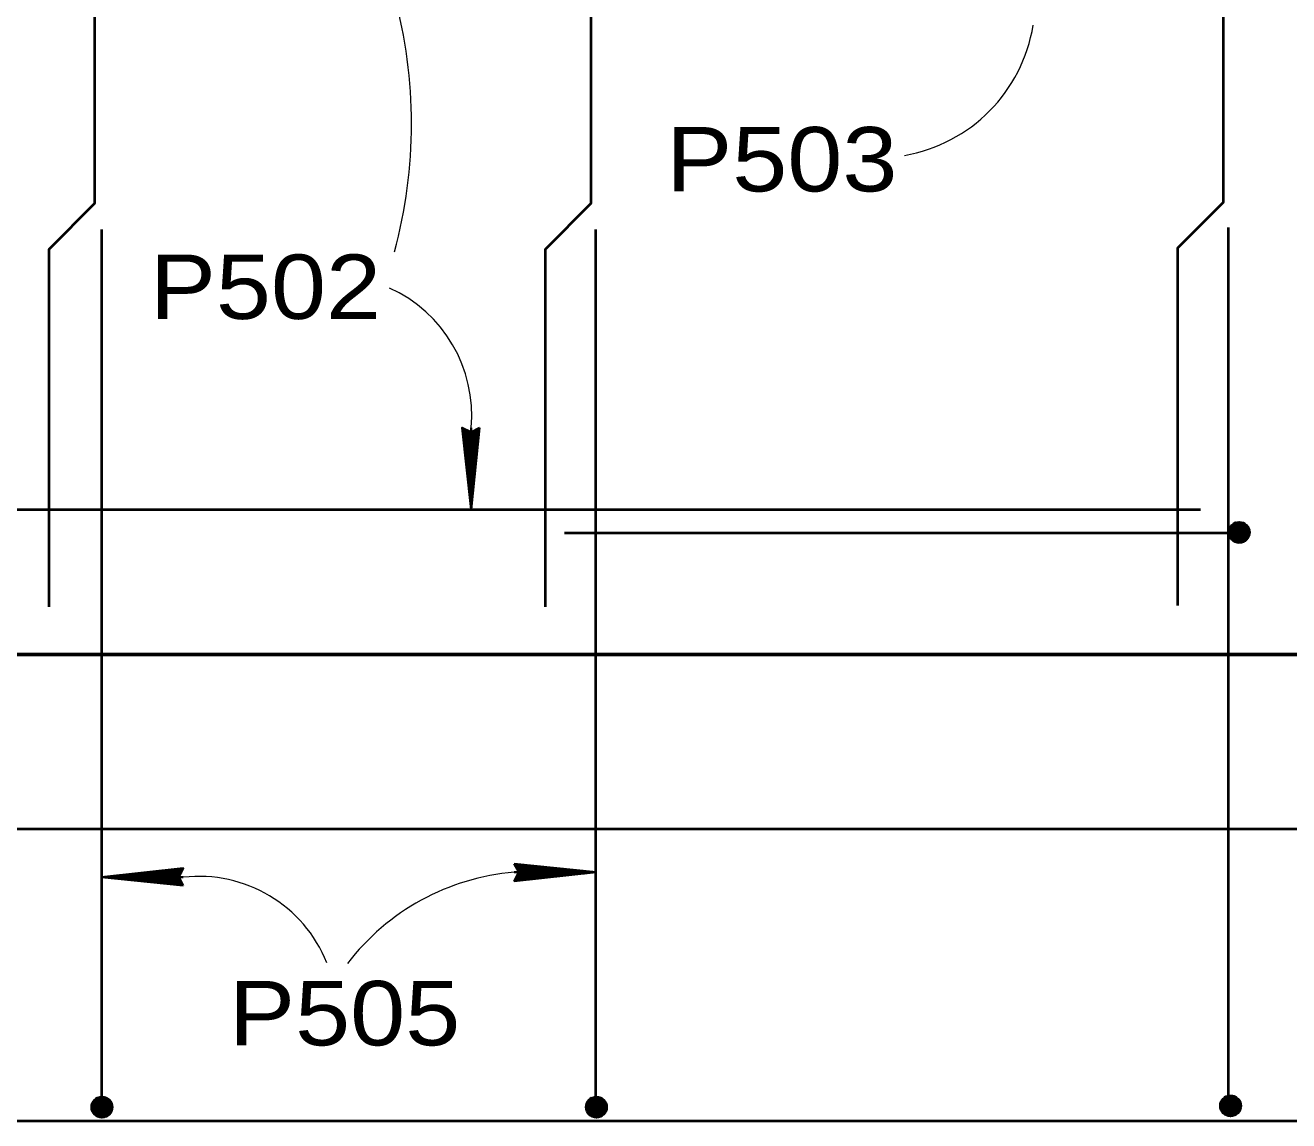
# Model space of a CAD drawing. Extents: x 4.49 to 7.69, y 0.28 to 2.27.
# Drawn here: x 5.2955 to 5.4591, y 0.6221 to 0.7638 of the extents above; entities that cross this region are included whole.
import ezdxf

# ---------------------------------------------------------------- set-up
doc = ezdxf.new("R2010")
doc.units = 0
doc.header["$LTSCALE"] = 0.0033
doc.layers.add('1', color=7, linetype='Continuous', lineweight=35)

msp = doc.modelspace()

# ---------------------------------------------------------------- linework, layer by layer
at = {"layer": '1', "lineweight": 40}
for p, q in [((5.45125, 0.737667), (5.45125, 0.625333)), ((5.305417, 0.737417), (5.305417, 0.624917)), ((5.369333, 0.737417), (5.369333, 0.625)), ((5.45175, 0.699), (5.451667, 0.6975)), ((5.451667, 0.6985), (5.453667, 0.698167)), ((5.451667, 0.698417), (5.453667, 0.698)), ((5.451667, 0.698333), (5.453583, 0.697917)), ((5.451833, 0.699), (5.45175, 0.6975)), ((5.45175, 0.699), (5.45375, 0.698667)), ((5.45175, 0.698917), (5.45375, 0.698583)), ((5.45175, 0.698833), (5.45375, 0.698417)), ((5.45175, 0.69875), (5.45375, 0.698333)), ((5.45175, 0.698583), (5.453667, 0.69825)), ((5.451833, 0.699167), (5.45375, 0.698833)), ((5.451917, 0.699), (5.451833, 0.6975)), ((5.452, 0.699), (5.451917, 0.6975)), ((5.452083, 0.699), (5.452, 0.6975)), ((5.45225, 0.699), (5.452167, 0.6975)), ((5.452333, 0.699), (5.45225, 0.6975)), ((5.452417, 0.699), (5.452333, 0.6975)), ((5.4525, 0.699), (5.452417, 0.6975)), ((5.452583, 0.699), (5.4525, 0.6975)), ((5.452667, 0.699), (5.452583, 0.6975)), ((5.45275, 0.699), (5.452667, 0.6975)), ((5.452917, 0.698917), (5.45275, 0.697417)), ((5.453083, 0.698917), (5.452917, 0.697417)), ((5.453167, 0.698917), (5.453083, 0.697417)), ((5.453167, 0.698917), (5.453083, 0.697417)), ((5.45325, 0.698917), (5.453167, 0.697417)), ((5.453333, 0.698917), (5.45325, 0.697417)), ((5.453417, 0.698917), (5.453333, 0.697417)), ((5.4535, 0.698917), (5.453417, 0.697417)), ((5.453583, 0.698917), (5.4535, 0.697417)), ((5.453667, 0.698917), (5.453583, 0.697417)), ((5.453833, 0.698917), (5.45375, 0.697417)), ((5.365333, 0.698167), (5.45125, 0.698167)), ((5.4515, 0.697583), (5.4535, 0.69725)), ((5.451583, 0.698083), (5.453583, 0.697667)), ((5.451583, 0.697833), (5.453583, 0.6975)), ((5.451583, 0.69775), (5.4535, 0.697417)), ((5.451583, 0.697667), (5.4535, 0.697333)), ((5.451667, 0.69825), (5.453583, 0.697833)), ((5.304833, 0.625), (5.3045, 0.623)), ((5.304917, 0.624917), (5.304583, 0.623)), ((5.305, 0.624917), (5.304667, 0.623)), ((5.305083, 0.624917), (5.30475, 0.622917)), ((5.30625, 0.62475), (5.30475, 0.624833)), ((5.30625, 0.624667), (5.30475, 0.62475)), ((5.305333, 0.624917), (5.304917, 0.622917)), ((5.3055, 0.624833), (5.305083, 0.622917)), ((5.305583, 0.624833), (5.305167, 0.622917)), ((5.305667, 0.624833), (5.30525, 0.622833)), ((5.30575, 0.624833), (5.305417, 0.622833)), ((5.305833, 0.62475), (5.3055, 0.622833)), ((5.306, 0.62475), (5.305583, 0.62275)), ((5.306083, 0.62475), (5.305667, 0.62275)), ((5.306167, 0.62475), (5.305833, 0.62275)), ((5.30625, 0.62475), (5.305917, 0.62275)), ((5.368833, 0.625), (5.3685, 0.623)), ((5.368917, 0.624917), (5.368583, 0.623)), ((5.369, 0.624917), (5.368667, 0.623)), ((5.369083, 0.624917), (5.36875, 0.622917)), ((5.37025, 0.62475), (5.36875, 0.624833)), ((5.37025, 0.624667), (5.36875, 0.62475)), ((5.369333, 0.624917), (5.368917, 0.622917)), ((5.3695, 0.624833), (5.369083, 0.622917)), ((5.369583, 0.624833), (5.369167, 0.622917)), ((5.369667, 0.624833), (5.36925, 0.622833)), ((5.36975, 0.624833), (5.369417, 0.622833)), ((5.369833, 0.62475), (5.3695, 0.622833)), ((5.37, 0.62475), (5.369583, 0.62275)), ((5.370083, 0.62475), (5.369667, 0.62275)), ((5.370167, 0.62475), (5.369833, 0.62275)), ((5.37025, 0.62475), (5.369917, 0.62275)), ((5.450917, 0.625167), (5.450583, 0.623167)), ((5.451, 0.625083), (5.450667, 0.623167)), ((5.451083, 0.625083), (5.45075, 0.623167)), ((5.451167, 0.625083), (5.450833, 0.623083)), ((5.452333, 0.624917), (5.450833, 0.625)), ((5.452333, 0.624833), (5.450833, 0.624917)), ((5.452333, 0.62475), (5.450833, 0.624833)), ((5.452333, 0.624667), (5.450833, 0.62475)), ((5.451417, 0.625083), (5.451, 0.623083)), ((5.451583, 0.625), (5.451167, 0.623083)), ((5.451667, 0.625), (5.45125, 0.623083)), ((5.45175, 0.625), (5.451333, 0.623)), ((5.451833, 0.625), (5.4515, 0.623)), ((5.451917, 0.624917), (5.451583, 0.623)), ((5.452083, 0.624917), (5.451667, 0.622917)), ((5.452167, 0.624917), (5.45175, 0.622917)), ((5.45225, 0.624917), (5.451917, 0.622917)), ((5.452333, 0.624917), (5.452, 0.622917)), ((5.4525, 0.624833), (5.452167, 0.622917)), ((5.306167, 0.623583), (5.304667, 0.62375)), ((5.306167, 0.623417), (5.304667, 0.623583)), ((5.306167, 0.623333), (5.304667, 0.623417)), ((5.306167, 0.623333), (5.304667, 0.623417)), ((5.306167, 0.62325), (5.304667, 0.623333)), ((5.306167, 0.623167), (5.304667, 0.62325)), ((5.306167, 0.623083), (5.304667, 0.623167)), ((5.30625, 0.624583), (5.30475, 0.624667)), ((5.30625, 0.6245), (5.30475, 0.624583)), ((5.30625, 0.624417), (5.30475, 0.6245)), ((5.30625, 0.62425), (5.30475, 0.624333)), ((5.30625, 0.624167), (5.30475, 0.62425)), ((5.30625, 0.624083), (5.30475, 0.624167)), ((5.30625, 0.624), (5.30475, 0.624083)), ((5.30625, 0.623917), (5.30475, 0.624)), ((5.30625, 0.623833), (5.30475, 0.623917)), ((5.30625, 0.62375), (5.30475, 0.623833)), ((5.306417, 0.624667), (5.306083, 0.62275)), ((5.370167, 0.623583), (5.368667, 0.62375)), ((5.370167, 0.623417), (5.368667, 0.623583)), ((5.370167, 0.623333), (5.368667, 0.623417)), ((5.370167, 0.623333), (5.368667, 0.623417)), ((5.370167, 0.62325), (5.368667, 0.623333)), ((5.370167, 0.623167), (5.368667, 0.62325)), ((5.370167, 0.623083), (5.368667, 0.623167)), ((5.37025, 0.624583), (5.36875, 0.624667)), ((5.37025, 0.6245), (5.36875, 0.624583)), ((5.37025, 0.624417), (5.36875, 0.6245)), ((5.37025, 0.62425), (5.36875, 0.624333)), ((5.37025, 0.624167), (5.36875, 0.62425)), ((5.37025, 0.624083), (5.36875, 0.624167)), ((5.37025, 0.624), (5.36875, 0.624083)), ((5.37025, 0.623917), (5.36875, 0.624)), ((5.37025, 0.623833), (5.36875, 0.623917)), ((5.37025, 0.62375), (5.36875, 0.623833)), ((5.370417, 0.624667), (5.370083, 0.62275)), ((5.45225, 0.62375), (5.45075, 0.623917)), ((5.45225, 0.623583), (5.45075, 0.62375)), ((5.45225, 0.6235), (5.45075, 0.623583)), ((5.45225, 0.6235), (5.45075, 0.623583)), ((5.45225, 0.623417), (5.45075, 0.6235)), ((5.45225, 0.623333), (5.45075, 0.623417)), ((5.45225, 0.62325), (5.45075, 0.623333)), ((5.45225, 0.623167), (5.45075, 0.62325)), ((5.45225, 0.623083), (5.45075, 0.623167)), ((5.452333, 0.624583), (5.450833, 0.624667)), ((5.452333, 0.624417), (5.450833, 0.6245)), ((5.452333, 0.624333), (5.450833, 0.624417)), ((5.452333, 0.62425), (5.450833, 0.624333)), ((5.452333, 0.624167), (5.450833, 0.62425)), ((5.452333, 0.624083), (5.450833, 0.624167)), ((5.452333, 0.624), (5.450833, 0.624083)), ((5.452333, 0.623917), (5.450833, 0.624)), ((5.306167, 0.623), (5.304667, 0.623083)), ((5.306167, 0.622917), (5.304667, 0.623)), ((5.306167, 0.622833), (5.304667, 0.622917)), ((5.306167, 0.622667), (5.304667, 0.62275)), ((5.370167, 0.623), (5.368667, 0.623083)), ((5.370167, 0.622917), (5.368667, 0.623)), ((5.370167, 0.622833), (5.368667, 0.622917)), ((5.370167, 0.622667), (5.368667, 0.62275)), ((5.45225, 0.623), (5.45075, 0.623083)), ((5.45225, 0.622833), (5.45075, 0.622917))]:
    msp.add_line(p, q, dxfattribs=at)
at = {"layer": '1'}
for p, q in [((5.352167, 0.7115), (5.353, 0.704167)), ((5.352333, 0.7115), (5.353083, 0.704167)), ((5.352417, 0.7115), (5.35325, 0.704167)), ((5.352583, 0.711583), (5.353333, 0.70425)), ((5.354083, 0.7115), (5.353083, 0.703667)), ((5.35325, 0.71175), (5.35325, 0.701167)), ((5.354083, 0.7115), (5.35325, 0.703667)), ((5.35425, 0.7115), (5.353333, 0.703667)), ((5.35425, 0.7115), (5.353333, 0.703667)), ((5.354167, 0.7115), (5.353333, 0.703667)), ((5.31575, 0.654667), (5.308417, 0.653833)), ((5.31575, 0.6545), (5.308417, 0.65375)), ((5.31575, 0.654417), (5.308417, 0.653583)), ((5.315833, 0.65425), (5.3085, 0.6535)), ((5.358833, 0.65425), (5.369417, 0.65425)), ((5.359, 0.653583), (5.366333, 0.654333)), ((5.359083, 0.65525), (5.366917, 0.654333)), ((5.359083, 0.65525), (5.366917, 0.654333)), ((5.359083, 0.655167), (5.366917, 0.654333)), ((5.359083, 0.655083), (5.366917, 0.65425)), ((5.359083, 0.655083), (5.366917, 0.654083)), ((5.359083, 0.653417), (5.366417, 0.65425)), ((5.316, 0.653583), (5.305417, 0.653583)), ((5.31575, 0.65275), (5.307917, 0.65375)), ((5.31575, 0.65275), (5.307917, 0.653583)), ((5.31575, 0.652583), (5.307917, 0.6535)), ((5.31575, 0.652583), (5.307917, 0.6535)), ((5.31575, 0.652667), (5.307917, 0.6535)), ((5.359083, 0.653333), (5.366417, 0.654083)), ((5.359083, 0.653167), (5.366417, 0.654))]:
    msp.add_line(p, q, dxfattribs=at)
at = {"layer": '1', "lineweight": 13}
for p, q in [((5.451333, 0.63175), (5.451333, 0.627833)), ((5.369333, 0.631), (5.369333, 0.623333))]:
    msp.add_line(p, q, dxfattribs=at)
at = {"layer": '1', "lineweight": 40}
for points in [[(5.298583, 0.998333), (5.298583, 0.955), (5.3045, 0.949083), (5.3045, 0.74075), (5.298583, 0.734833), (5.298583, 0.688583)], [(5.362833, 0.998333), (5.362833, 0.955), (5.36875, 0.949083), (5.36875, 0.74075), (5.362833, 0.734833), (5.362833, 0.688583)], [(5.444667, 0.9985), (5.444667, 0.955167), (5.450583, 0.94925), (5.450583, 0.740917), (5.444667, 0.735), (5.444667, 0.68875)], [(4.89675, 0.701167), (5.122333, 0.701167), (5.447667, 0.701167)], [(5.451333, 0.698167), (5.453917, 0.6985), (5.451583, 0.699), (5.453917, 0.697917), (5.4515, 0.6975), (5.4535, 0.697167), (5.4535, 0.69925), (5.452583, 0.696917), (5.452833, 0.6995), (5.451833, 0.697167), (5.452167, 0.6995), (5.453, 0.696917), (5.451417, 0.698667), (5.453833, 0.698833), (5.452167, 0.697), (5.45325, 0.699417), (5.451583, 0.699), (5.4515, 0.6975), (5.452583, 0.696917), (5.4535, 0.697167), (5.453917, 0.697917), (5.453833, 0.698833), (5.45325, 0.699417), (5.452583, 0.698333), (5.45375, 0.697417), (5.451833, 0.697167), (5.452583, 0.698333), (5.4515, 0.698833), (5.4525, 0.6995), (5.452583, 0.698417), (5.453417, 0.697167), (5.451417, 0.698417), (5.45275, 0.69875), (5.4535, 0.69925)], [(5.12225, 0.664), (5.184583, 0.664), (5.191833, 0.659833), (5.52725, 0.659833)], [(5.122333, 0.62625), (5.183917, 0.62625), (5.191167, 0.622083), (5.528083, 0.622083)], [(5.305417, 0.625167), (5.30575, 0.622583), (5.30625, 0.624917), (5.305167, 0.622583), (5.30475, 0.625), (5.304417, 0.623), (5.3065, 0.623), (5.304167, 0.623917), (5.30675, 0.623667), (5.304417, 0.624667), (5.30675, 0.624333), (5.304167, 0.6235), (5.305917, 0.625083), (5.306083, 0.622667), (5.30425, 0.624333), (5.306667, 0.62325), (5.30625, 0.624917), (5.30475, 0.625), (5.304167, 0.623917), (5.304417, 0.623), (5.305167, 0.622583), (5.306083, 0.622667), (5.306667, 0.62325), (5.305583, 0.623917), (5.304667, 0.62275), (5.304417, 0.624667), (5.305583, 0.623917), (5.306083, 0.625), (5.30675, 0.624), (5.305667, 0.623917), (5.304417, 0.623083), (5.305667, 0.625083), (5.306, 0.62375), (5.3065, 0.623)], [(5.369417, 0.625167), (5.36975, 0.622583), (5.37025, 0.624917), (5.369167, 0.622583), (5.36875, 0.625), (5.368417, 0.623), (5.3705, 0.623), (5.368167, 0.623917), (5.37075, 0.623667), (5.368417, 0.624667), (5.37075, 0.624333), (5.368167, 0.6235), (5.369917, 0.625083), (5.370083, 0.622667), (5.36825, 0.624333), (5.370667, 0.62325), (5.37025, 0.624917), (5.36875, 0.625), (5.368167, 0.623917), (5.368417, 0.623), (5.369167, 0.622583), (5.370083, 0.622667), (5.370667, 0.62325), (5.369583, 0.623917), (5.368667, 0.62275), (5.368417, 0.624667), (5.369583, 0.623917), (5.370083, 0.625), (5.37075, 0.624), (5.369667, 0.623917), (5.368417, 0.623083), (5.369667, 0.625083), (5.37, 0.62375), (5.3705, 0.623)], [(5.4515, 0.625333), (5.451833, 0.62275), (5.452333, 0.625083), (5.45125, 0.62275), (5.450833, 0.625167), (5.4505, 0.623167), (5.452583, 0.623167), (5.45025, 0.624083), (5.452833, 0.623833), (5.4505, 0.624833), (5.452833, 0.6245), (5.45025, 0.623667), (5.452, 0.62525), (5.452167, 0.622833), (5.450333, 0.6245), (5.45275, 0.623417), (5.452333, 0.625083), (5.450833, 0.625167), (5.45025, 0.624083), (5.4505, 0.623167), (5.45125, 0.62275), (5.452167, 0.622833), (5.45275, 0.623417), (5.451667, 0.624083), (5.45075, 0.622917), (5.4505, 0.624833), (5.451667, 0.624083), (5.452167, 0.625167), (5.452833, 0.624167), (5.45175, 0.624083), (5.4505, 0.62325), (5.45175, 0.62525), (5.452083, 0.623917), (5.452583, 0.623167)]]:
    msp.add_lwpolyline(points, dxfattribs=at)
at = {"layer": '1'}
for points in [[(5.354333, 0.71175), (5.35325, 0.701167), (5.352083, 0.71175), (5.35325, 0.711167)], [(5.353333, 0.711), (5.353417, 0.706333), (5.353333, 0.706333), (5.353333, 0.70725), (5.353417, 0.711), (5.3535, 0.708), (5.353583, 0.711167), (5.353667, 0.708917), (5.35375, 0.711167), (5.3535, 0.707667), (5.353333, 0.703), (5.353083, 0.703917), (5.353083, 0.702667), (5.353083, 0.711), (5.352917, 0.708583), (5.352917, 0.711167), (5.353333, 0.705833), (5.352667, 0.711167)], [(5.316, 0.6525), (5.305417, 0.653583), (5.316, 0.65475), (5.315417, 0.653583)], [(5.31525, 0.6535), (5.310583, 0.653417), (5.310583, 0.6535), (5.3115, 0.6535), (5.31525, 0.653417), (5.31225, 0.653333), (5.315417, 0.65325), (5.313167, 0.653167), (5.315417, 0.653083), (5.311917, 0.653333), (5.30725, 0.6535), (5.308167, 0.65375), (5.306917, 0.65375), (5.31525, 0.65375), (5.312833, 0.653917), (5.315417, 0.653917), (5.310083, 0.6535), (5.315417, 0.654167)], [(5.358833, 0.655333), (5.369417, 0.65425), (5.358833, 0.653083), (5.359417, 0.65425)], [(5.359583, 0.654333), (5.36425, 0.654417), (5.36425, 0.654333), (5.363333, 0.654333), (5.359583, 0.654417), (5.362583, 0.6545), (5.359417, 0.654583), (5.361667, 0.654667), (5.359417, 0.65475), (5.362917, 0.6545), (5.367583, 0.654333), (5.366667, 0.654083), (5.367917, 0.654083), (5.359583, 0.654083), (5.362, 0.653917), (5.359417, 0.653917), (5.36475, 0.654333), (5.359417, 0.653667)]]:
    msp.add_lwpolyline(points, close=True, dxfattribs=at)
for points in [[(5.353333, 0.711), (5.354083, 0.711417), (5.353833, 0.711167), (5.3535, 0.711), (5.353583, 0.71075), (5.353917, 0.710917), (5.353167, 0.711083), (5.352667, 0.71125), (5.35225, 0.7115)], [(5.31525, 0.6535), (5.315667, 0.65275), (5.315417, 0.653), (5.31525, 0.653333), (5.315, 0.65325), (5.315167, 0.652917), (5.315333, 0.653667), (5.3155, 0.654167), (5.31575, 0.654583)], [(5.359583, 0.654333), (5.359167, 0.655083), (5.359417, 0.654833), (5.359583, 0.6545), (5.359833, 0.654583), (5.359667, 0.654917), (5.3595, 0.654167), (5.359333, 0.653667), (5.359083, 0.65325)]]:
    msp.add_lwpolyline(points, dxfattribs=at)
at = {"layer": '1', "lineweight": 60}
msp.add_lwpolyline([(4.879083, 0.682417), (5.12225, 0.682417), (5.462417, 0.682417)], dxfattribs=at)
at = {"layer": '1', "lineweight": 40}
for centre in [(5.452667, 0.698217), (5.305467, 0.623833), (5.369467, 0.623833), (5.45155, 0.624)]:
    msp.add_circle(centre, 0.00132, dxfattribs=at)
at = {"layer": '1', "lineweight": 13}
for centre, radius, start, end in [((5.282122, 0.751083), 0.063418, 344.84139, 15.15861), ((5.405864, 0.767102), 0.0204, 279.79151, 350.77859), ((5.335337, 0.713405), 0.017989, 354.72179, 65.95511), ((5.361396, 0.623977), 0.030382, 94.83783, 142.63079), ((5.318048, 0.635896), 0.017806, 21.77133, 96.60391)]:
    msp.add_arc(centre, radius, start, end, dxfattribs=at)

# ---------------------------------------------------------------- texts
at = {"layer": '1', "width": 1.15}
for s, p in [('P503', (5.3785, 0.742333)), ('P502', (5.311667, 0.725833)), ('P505', (5.321917, 0.631833))]:
    msp.add_text(s, height=0.008334, dxfattribs=at).set_placement(p)

doc.saveas('drawing.dxf')
